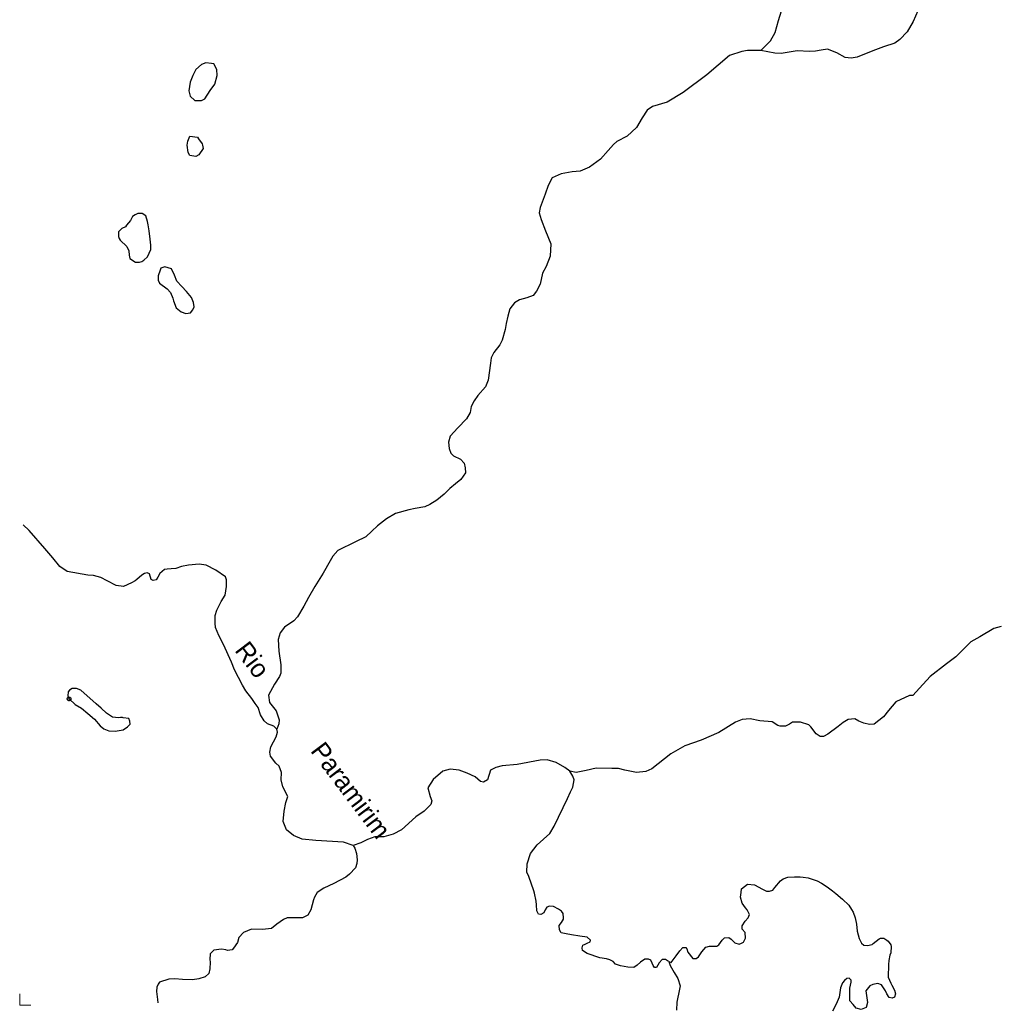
# Model space of a CAD drawing. Extents: x 717.8 to 772.7, y 8672.2 to 8728.
# Drawn here: x 717.77 to 728.35, y 8672.58 to 8683.34 of the extents above; entities that cross this region are included whole.
import ezdxf
from ezdxf.enums import TextEntityAlignment as Align

# ---------------------------------------------------------------- set-up
doc = ezdxf.new("R2010")
doc.units = 0
doc.header["$LTSCALE"] = 0.08
doc.header["$PDMODE"] = 32
doc.header["$PDSIZE"] = 0.04
doc.linetypes.add('LONG_DASHED', pattern=[7.5, 6, -1.5])
for name, color, linetype, lineweight in [('3', 7, 'LONG_DASHED', 25), ('63', 7, 'Continuous', 13), ('9', 7, 'LONG_DASHED', 25)]:
    doc.layers.add(name, color=color, linetype=linetype, lineweight=lineweight)
doc.layers.add('61', color=7, linetype='Continuous')

msp = doc.modelspace()

# ---------------------------------------------------------------- linework, layer by layer
at = {"layer": '3'}
for points in [[(719.8737, 8682.8597), (719.8507, 8682.8662), (719.7885, 8682.8737), (719.7401, 8682.8552), (719.6793, 8682.8), (719.6462, 8682.7337), (719.6187, 8682.6618), (719.6021, 8682.5679), (719.6177, 8682.5101), (719.6685, 8682.4631), (719.7418, 8682.4618), (719.7785, 8682.4802), (719.8344, 8682.5733), (719.8841, 8682.6396), (719.9114, 8682.7336), (719.9071, 8682.7983)], [(719.6968, 8682.0649), (719.7079, 8682.0484), (719.7466, 8681.993), (719.7522, 8681.9764), (719.7577, 8681.9433), (719.7136, 8681.8714), (719.6804, 8681.8549), (719.614, 8681.866), (719.5974, 8681.8991), (719.5863, 8681.9765), (719.5917, 8682.0207), (719.6138, 8682.076)], [(719.098, 8681.2349), (719.0485, 8681.237), (719.0216, 8681.2223), (718.9925, 8681.203), (718.9684, 8681.1594), (718.9269, 8681.1079), (718.9147, 8681.0929), (718.8739, 8681.0739), (718.84, 8681.0364), (718.839, 8680.988), (718.8474, 8680.9656), (718.857, 8680.9462), (718.9298, 8680.8783), (718.9508, 8680.8314), (718.9565, 8680.7826), (718.9638, 8680.7474), (719.023, 8680.709), (719.0684, 8680.7074), (719.0909, 8680.716), (719.1141, 8680.728), (719.1528, 8680.7668), (719.1915, 8680.8443), (719.1915, 8680.8928), (719.1818, 8680.9558), (719.1723, 8681.0488), (719.1617, 8681.1118), (719.1539, 8681.1479), (719.1377, 8681.2101)], [(719.3006, 8680.6421), (719.2913, 8680.6216), (719.2695, 8680.5577), (719.2695, 8680.5141), (719.2838, 8680.4808), (719.2829, 8680.4804), (719.3677, 8680.4174), (719.4047, 8680.3788), (719.4292, 8680.316), (719.4374, 8680.2864), (719.4652, 8680.2124), (719.5181, 8680.1671), (719.5698, 8680.1511), (719.6197, 8680.1578), (719.6473, 8680.1899), (719.6618, 8680.2238), (719.6533, 8680.2687), (719.6323, 8680.3225), (719.5794, 8680.3886), (719.5261, 8680.4419), (719.4744, 8680.5023), (719.4485, 8680.568), (719.4139, 8680.6348), (719.3434, 8680.6586)], [(718.3818, 8676.0803), (718.3368, 8676.0773), (718.3053, 8676.0623), (718.2928, 8676.0412), (718.2883, 8675.9987), (718.3028, 8675.9659), (718.3693, 8675.9067), (718.4384, 8675.8652), (718.5076, 8675.8078), (718.5784, 8675.7445), (718.6393, 8675.674), (718.6798, 8675.6409), (718.7329, 8675.6204), (718.8044, 8675.6139), (718.8899, 8675.6294), (718.9374, 8675.6614), (718.9643, 8675.6899), (718.9634, 8675.724), (718.9529, 8675.754), (718.8914, 8675.762), (718.8818, 8675.7633), (718.8594, 8675.7628), (718.8384, 8675.762), (718.7734, 8675.7665), (718.7078, 8675.8105), (718.6493, 8675.8637), (718.5983, 8675.9113), (718.4289, 8676.0593)]]:
    msp.add_lwpolyline(points, close=True, dxfattribs=at)
msp.add_point((718.3028, 8675.9659), dxfattribs=at)
at = {"layer": '63'}
msp.add_lwpolyline([(717.7675, 8672.7638), (717.7675, 8672.6406), (717.8889, 8672.6406)], dxfattribs=at)
at = {"layer": '9'}
for p, q in [((723.8111, 8675.1649), (723.743, 8675.1796)), ((719.2625, 8672.7031), (719.2676, 8672.6672))]:
    msp.add_line(p, q, dxfattribs=at)
for points in [[(725.8152, 8683.0053), (725.9225, 8683.1097), (725.9699, 8683.2005), (726.0088, 8683.3324), (726.0733, 8683.5432)], [(727.5197, 8683.4368), (727.4687, 8683.3211), (727.4061, 8683.2092), (727.3271, 8683.1237), (727.2718, 8683.0849), (727.147, 8683.0442), (727.0311, 8683.003), (726.8638, 8682.9347), (726.7985, 8682.9233), (726.731, 8682.9312), (726.6419, 8682.9793), (726.5399, 8683.0217), (726.4709, 8683.0104), (726.4106, 8682.9974), (726.3444, 8682.9949), (726.2109, 8683.0025), (726.035, 8682.9752), (725.9674, 8682.9759), (725.8152, 8683.0053)], [(725.8152, 8683.0053), (725.6712, 8683.0061), (725.6084, 8682.9953), (725.4762, 8682.9505), (725.2285, 8682.743), (724.9735, 8682.5483), (724.7973, 8682.4462), (724.6382, 8682.3973), (724.5827, 8682.3592), (724.5278, 8682.2766), (724.4663, 8682.1693), (724.3652, 8682.0753), (724.2521, 8682.0183), (724.2139, 8681.9848), (724.1561, 8681.9188), (724.0734, 8681.8279), (723.9544, 8681.7407), (723.8521, 8681.695), (723.768, 8681.6904), (723.6469, 8681.6677), (723.5501, 8681.6234), (723.5065, 8681.5416), (723.4728, 8681.4453), (723.4205, 8681.3029), (723.4084, 8681.2443), (723.4296, 8681.1719), (723.477, 8681.0487), (723.535, 8680.9072), (723.5273, 8680.7744), (723.4844, 8680.6613), (723.4436, 8680.5885), (723.4174, 8680.4674), (723.3775, 8680.3938), (723.3428, 8680.3471), (723.2737, 8680.3197), (723.1951, 8680.2997), (723.1406, 8680.2673), (723.0912, 8680.2023), (723.0675, 8680.1224), (723.0493, 8680.0404), (723.0389, 8679.9768), (723.0057, 8679.8607), (722.9807, 8679.8116), (722.9151, 8679.726), (722.8869, 8679.6673), (722.8806, 8679.6115), (722.8555, 8679.4267), (722.8242, 8679.3545), (722.7423, 8679.2614), (722.7015, 8679.2019), (722.6695, 8679.142), (722.6587, 8679.0766), (722.62, 8679.0059), (722.5263, 8678.9086), (722.4424, 8678.8177), (722.4241, 8678.7528), (722.4312, 8678.6863), (722.4489, 8678.6331), (722.478, 8678.6032), (722.5549, 8678.569), (722.5926, 8678.5254), (722.6046, 8678.4736), (722.6092, 8678.4187), (722.5585, 8678.3492), (722.4995, 8678.3017), (722.4384, 8678.2504), (722.3751, 8678.1882), (722.2983, 8678.1243), (722.2205, 8678.0774), (722.1673, 8678.0507), (722.0617, 8678.0346), (721.9913, 8678.0201), (721.8475, 8677.9777), (721.7484, 8677.92), (721.6519, 8677.8442), (721.591, 8677.7877), (721.5262, 8677.7261), (721.4134, 8677.6714), (721.2223, 8677.5753), (721.1673, 8677.5139), (721.1375, 8677.4634), (721.0627, 8677.3317), (720.9717, 8677.1872), (720.9022, 8677.0664), (720.8508, 8676.9734), (720.7832, 8676.858), (720.7442, 8676.8151), (720.6414, 8676.7429), (720.5939, 8676.6838), (720.5747, 8676.6112), (720.5803, 8676.4854), (720.602, 8676.3356), (720.602, 8676.2445), (720.5866, 8676.2075), (720.5334, 8676.1245)], [(719.0398, 8677.2633), (719.0208, 8677.2489), (718.9809, 8677.2249), (718.8935, 8677.185), (718.8149, 8677.1955), (718.7174, 8677.2466), (718.6464, 8677.2826), (718.5683, 8677.3039), (718.5055, 8677.3082), (718.2821, 8677.3489), (718.2017, 8677.4019), (718.1246, 8677.4962), (718.0374, 8677.5996), (717.8694, 8677.793), (717.8052, 8677.8541)], [(720.5605, 8675.6378), (720.5262, 8675.6706), (720.4574, 8675.6967), (720.4214, 8675.7268), (720.3824, 8675.7925), (720.3559, 8675.8721), (720.3242, 8675.9142), (720.2882, 8675.9719), (720.2232, 8676.0522), (720.1845, 8676.1163), (720.0998, 8676.2822), (720.0681, 8676.3647), (719.9809, 8676.5562), (719.9284, 8676.6529), (719.8932, 8676.7404), (719.8881, 8676.7878), (719.8886, 8676.8703), (719.9089, 8676.9276), (719.9535, 8677.0223), (719.9974, 8677.0904), (720.0135, 8677.186), (720.0136, 8677.2577), (720.0031, 8677.2923), (719.8958, 8677.3653), (719.7921, 8677.4172), (719.7151, 8677.4272), (719.5988, 8677.4177), (719.5239, 8677.4037), (719.4613, 8677.3812), (719.4098, 8677.3766)], [(719.4098, 8677.3766), (719.3687, 8677.373), (719.3376, 8677.3712), (719.2868, 8677.3256), (719.265, 8677.2887), (719.2469, 8677.2579), (719.217, 8677.2528), (719.1942, 8677.2635), (719.1744, 8677.3225), (719.1501, 8677.3343), (719.1212, 8677.3275), (719.0927, 8677.3078), (719.0398, 8677.2633)], [(728.4265, 8676.751), (728.3454, 8676.7299), (728.1955, 8676.6397), (728.0965, 8676.5871), (727.9327, 8676.4232), (727.832, 8676.3472), (727.6544, 8676.2099), (727.5382, 8676.0835), (727.4659, 8676.0039), (727.4313, 8676.0014), (727.2823, 8675.9345), (727.2027, 8675.8386), (727.1467, 8675.7709), (727.0455, 8675.6907), (726.9962, 8675.6881), (726.934, 8675.701), (726.8809, 8675.7238), (726.8361, 8675.7477), (726.7658, 8675.7435), (726.7096, 8675.71), (726.6561, 8675.6644), (726.5426, 8675.5818), (726.4949, 8675.5578), (726.4619, 8675.5588), (726.4176, 8675.5852), (726.3596, 8675.6615), (726.3358, 8675.6854), (726.2456, 8675.7135), (726.1607, 8675.7116), (726.1289, 8675.6932), (726.0826, 8675.6703), (726.0267, 8675.6686), (726.0012, 8675.677), (725.9381, 8675.717), (725.8037, 8675.7276), (725.6995, 8675.7486), (725.612, 8675.7405), (725.5399, 8675.7144), (725.3599, 8675.6023), (725.1667, 8675.5161), (724.9895, 8675.4569), (724.8391, 8675.3705), (724.6307, 8675.2057), (724.566, 8675.1783), (724.4651, 8675.1666), (724.3383, 8675.1931), (724.2712, 8675.2097), (724.1965, 8675.2115), (724.0266, 8675.2122), (723.9181, 8675.1876), (723.8111, 8675.1649)], [(720.5334, 8676.1245), (720.4685, 8676.0053), (720.4798, 8675.9283), (720.5524, 8675.8375), (720.5833, 8675.7378), (720.5819, 8675.6967), (720.5605, 8675.6378)], [(721.3872, 8674.3755), (721.284, 8674.4106), (720.9826, 8674.428), (720.8341, 8674.444), (720.7406, 8674.4813), (720.6647, 8674.544), (720.6282, 8674.6331), (720.6377, 8674.7484), (720.6559, 8674.8404), (720.677, 8674.9047), (720.6237, 8675.0127), (720.6069, 8675.0872), (720.6084, 8675.1653), (720.585, 8675.2339), (720.5477, 8675.2683), (720.4886, 8675.3435), (720.4828, 8675.388), (720.4923, 8675.4442), (720.5529, 8675.5551), (720.5666, 8675.6046), (720.5605, 8675.6378)], [(723.743, 8675.1796), (723.6874, 8675.2197), (723.5919, 8675.2759), (723.4948, 8675.3033), (723.4202, 8675.3008), (723.1682, 8675.2536), (723.0057, 8675.2386), (722.9378, 8675.222), (722.8802, 8675.1913), (722.8474, 8675.0855), (722.8041, 8675.0621), (722.7707, 8675.0698), (722.7143, 8675.1184), (722.6248, 8675.1582), (722.5411, 8675.193), (722.4408, 8675.2046), (722.3606, 8675.1795), (722.2575, 8675.0906), (722.1995, 8675.0019), (722.2255, 8674.9074), (722.2414, 8674.8592), (722.2332, 8674.8189), (722.1602, 8674.7468), (722.0699, 8674.6838), (721.9124, 8674.5436), (721.8214, 8674.4955), (721.7219, 8674.469), (721.6241, 8674.469), (721.5421, 8674.4375), (721.4699, 8674.4035), (721.3872, 8674.3755)], [(724.8168, 8673.1136), (724.8014, 8673.1233), (724.7791, 8673.1366), (724.7434, 8673.135), (724.7111, 8673.1015), (724.6833, 8673.0507), (724.6609, 8673.0477), (724.6477, 8673.0711), (724.6372, 8673.0972), (724.6205, 8673.1274), (724.5974, 8673.1406), (724.5556, 8673.1402), (724.509, 8673.108), (724.4741, 8673.073), (724.4363, 8673.0509), (724.3712, 8673.0521), (724.2903, 8673.069), (724.2365, 8673.0871), (724.2124, 8673.1156), (724.1774, 8673.1321), (724.1411, 8673.1428), (724.0675, 8673.1553), (723.928, 8673.2027), (723.8794, 8673.2345), (723.8745, 8673.263), (723.8826, 8673.2902), (723.9075, 8673.3035), (723.9288, 8673.3119), (723.9628, 8673.3286), (723.967, 8673.3474), (723.9304, 8673.3772), (723.8501, 8673.3887), (723.7586, 8673.405), (723.7027, 8673.4137), (723.6465, 8673.4275), (723.6274, 8673.4573), (723.625, 8673.5044), (723.6495, 8673.5377), (723.6732, 8673.5755), (723.6723, 8673.5876), (723.6696, 8673.6359), (723.6507, 8673.6616), (723.6165, 8673.6845), (723.5623, 8673.7123), (723.52, 8673.7151), (723.4923, 8673.7038), (723.4718, 8673.6745), (723.4606, 8673.6431), (723.4252, 8673.6238), (723.3999, 8673.6282), (723.3842, 8673.6644), (723.381, 8673.7292), (723.3747, 8673.7702), (723.3575, 8673.8572), (723.3519, 8673.8817), (723.2957, 8674.0381), (723.2741, 8674.086), (723.2765, 8674.1767), (723.3152, 8674.2875), (723.3854, 8674.3821), (723.5241, 8674.5037), (723.571, 8674.5851), (723.7153, 8674.8855), (723.7478, 8674.9579), (723.7755, 8675.0074), (723.7871, 8675.0886), (723.7735, 8675.1271), (723.743, 8675.1796)], [(721.3872, 8674.3755), (721.4065, 8674.346), (721.4251, 8674.2872), (721.431, 8674.2186), (721.427, 8674.1775), (721.414, 8674.1303), (721.3496, 8674.0625), (721.3089, 8674.0297), (721.1786, 8673.9599), (721.0686, 8673.9107), (720.997, 8673.8622), (720.9685, 8673.8129), (720.9564, 8673.7841), (720.9281, 8673.6766), (720.8965, 8673.6177), (720.8362, 8673.5897), (720.7464, 8673.5904), (720.6696, 8673.5875), (720.6315, 8673.5717), (720.5573, 8673.5212), (720.5003, 8673.4719), (720.4026, 8673.4637), (720.2831, 8673.4642), (720.1962, 8673.4297), (720.1445, 8673.3766), (720.1319, 8673.3196), (720.0891, 8673.2582), (720.0728, 8673.2418), (720.0239, 8673.2335), (720.0035, 8673.2417), (719.9587, 8673.2499), (719.8731, 8673.2376), (719.8364, 8673.1964), (719.8325, 8673.1347), (719.8335, 8673.1088), (719.8326, 8673.036), (719.8192, 8672.9846), (719.7818, 8672.9493), (719.7122, 8672.9256), (719.6432, 8672.917), (719.5348, 8672.9184), (719.4499, 8672.9248), (719.3846, 8672.9244), (719.2841, 8672.8892), (719.2719, 8672.8684), (719.2554, 8672.8375), (719.2518, 8672.7886), (719.2625, 8672.7031)], [(725.1767, 8673.2197), (725.2193, 8673.2704), (725.2578, 8673.2803), (725.3384, 8673.2795), (725.3613, 8673.2964), (725.3956, 8673.3457), (725.4212, 8673.3712), (725.4687, 8673.3748), (725.4924, 8673.3559), (725.533, 8673.3177), (725.5804, 8673.3036), (725.6043, 8673.3125), (725.6264, 8673.3236), (725.6494, 8673.369), (725.6446, 8673.4285), (725.6133, 8673.4647), (725.6129, 8673.5017), (725.647, 8673.5528), (725.6775, 8673.5876), (725.6912, 8673.6256), (725.6667, 8673.6757), (725.649, 8673.6958), (725.612, 8673.7481), (725.5947, 8673.8136), (725.6005, 8673.8643), (725.6048, 8673.9034), (725.6711, 8673.9525), (725.7466, 8673.9465), (725.8339, 8673.9011), (725.8789, 8673.8781), (725.9102, 8673.8773), (725.9444, 8673.889), (725.9661, 8673.9188), (726.031, 8673.9908), (726.0598, 8674.0125), (726.1086, 8674.0301), (726.1825, 8674.0334), (726.2421, 8674.0346), (726.2765, 8674.0304), (726.3282, 8674.0218), (726.4273, 8673.9915), (726.4747, 8673.9656), (726.535, 8673.9266), (726.5954, 8673.8832), (726.6298, 8673.853), (726.7032, 8673.7923), (726.7721, 8673.7272), (726.8014, 8673.6801), (726.8197, 8673.6492), (726.8412, 8673.5885), (726.854, 8673.5201), (726.8609, 8673.4441), (726.8834, 8673.3645), (726.9097, 8673.3125), (726.9356, 8673.2901), (726.9754, 8673.2869), (727.0241, 8673.2993), (727.0347, 8673.3084), (727.0993, 8673.3607), (727.1162, 8673.3683), (727.1508, 8673.3663), (727.1857, 8673.3466), (727.1983, 8673.3347), (727.2285, 8673.2956), (727.2328, 8673.2783), (727.2271, 8673.2097), (727.2156, 8673.1827), (727.2062, 8673.1261), (727.2029, 8673.0829), (727.1987, 8672.944), (727.2289, 8672.8788), (727.2375, 8672.8572), (727.2674, 8672.8024), (727.2778, 8672.7638), (727.2678, 8672.7271), (727.2424, 8672.7168), (727.2099, 8672.7244), (727.185, 8672.7625), (727.1693, 8672.7944), (727.1255, 8672.8613), (727.0867, 8672.8743), (727.0307, 8672.8655), (727.0008, 8672.8514), (726.9562, 8672.7975), (726.9748, 8672.6681), (726.9599, 8672.6147), (726.9044, 8672.5917), (726.8518, 8672.6082), (726.8176, 8672.6484), (726.7834, 8672.6862), (726.7828, 8672.8263), (726.7981, 8672.8913), (726.7981, 8672.9129), (726.7765, 8672.9347), (726.7506, 8672.9302)], [(724.8168, 8673.1136), (724.8411, 8673.1044), (724.8965, 8673.1743), (724.9349, 8673.232), (724.9676, 8673.2672), (725.0006, 8673.2648), (725.0131, 8673.2511), (725.0232, 8673.2151), (725.0766, 8673.1464), (725.1128, 8673.1466), (725.1405, 8673.1651), (725.1767, 8673.2197)], [(724.8168, 8673.1136), (724.8302, 8673.0719), (724.8729, 8672.9964), (724.916, 8672.9314), (724.9387, 8672.852), (724.9248, 8672.7794), (724.9112, 8672.7074), (724.904, 8672.6735), (724.8991, 8672.5879)], [(726.7506, 8672.9302), (726.7249, 8672.9085), (726.7034, 8672.8824), (726.6805, 8672.8292), (726.6648, 8672.7255), (726.6346, 8672.6521), (726.5953, 8672.5752)]]:
    msp.add_lwpolyline(points, dxfattribs=at)

# ---------------------------------------------------------------- texts
at = {"layer": '61'}
msp.add_text('Rio             Paramirim', height=0.2, rotation=306.997, dxfattribs=at).set_placement((720.8718, 8675.4592), align=Align.CENTER)

doc.saveas('drawing.dxf')
